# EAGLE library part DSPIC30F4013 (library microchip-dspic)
dsPIC General DSP with CAN and I2S ports
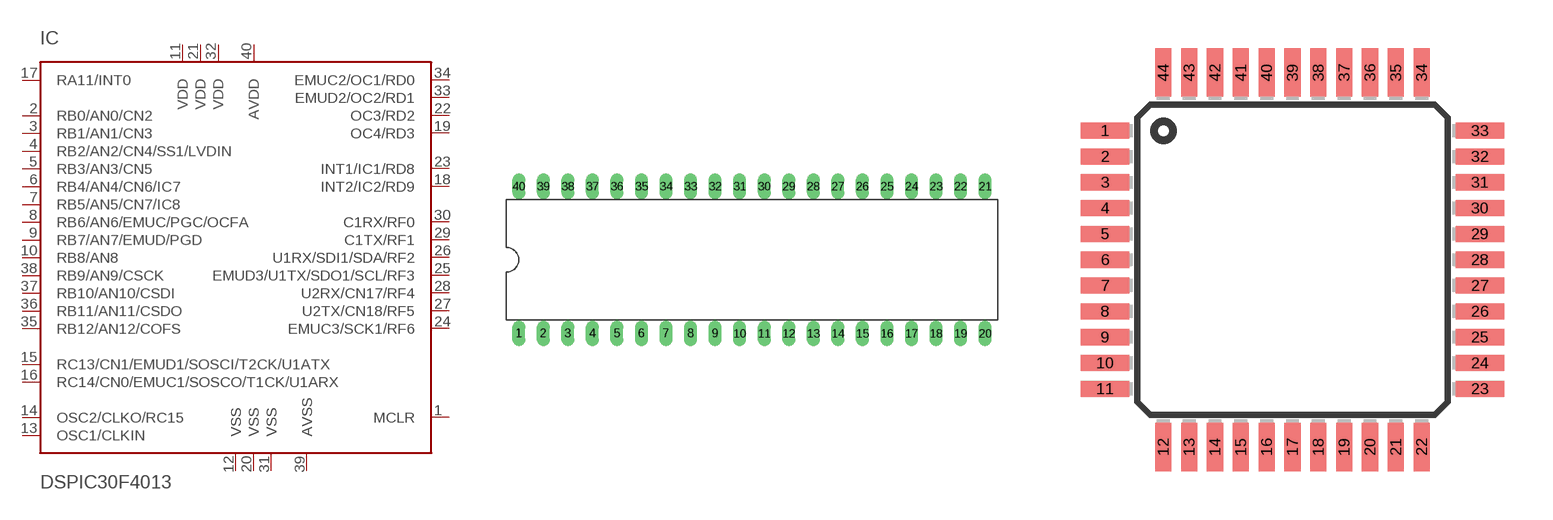
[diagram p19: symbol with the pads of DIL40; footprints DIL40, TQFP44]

Designator prefix IC

## DSPIC30F4013/P  [DIL40]
1  MCLR  in
2  RB0/AN0/CN2
3  RB1/AN1/CN3
4  RB2/AN2/CN4/SS1/LVDIN
5  RB3/AN3/CN5
6  RB4/AN4/CN6/IC7
7  RB5/AN5/CN7/IC8
8  RB6/AN6/EMUC/PGC/OCFA
9  RB7/AN7/EMUD/PGD
10  RB8/AN8
11  VDD  pwr
12  VSS  pwr
13  OSC1/CLKIN  in
14  OSC2/CLKO/RC15
15  RC13/CN1/EMUD1/SOSCI/T2CK/U1ATX
16  RC14/CN0/EMUC1/SOSCO/T1CK/U1ARX
17  RA11/INT0
18  INT2/IC2/RD9
19  OC4/RD3
20  VSS  pwr
21  VDD  pwr
22  OC3/RD2
23  INT1/IC1/RD8
24  EMUC3/SCK1/RF6
25  EMUD3/U1TX/SDO1/SCL/RF3
26  U1RX/SDI1/SDA/RF2
27  U2TX/CN18/RF5
28  U2RX/CN17/RF4
29  C1TX/RF1
30  C1RX/RF0
31  VSS  pwr
32  VDD  pwr
33  EMUD2/OC2/RD1
34  EMUC2/OC1/RD0
35  RB12/AN12/COFS
36  RB11/AN11/CSDO
37  RB10/AN10/CSDI
38  RB9/AN9/CSCK
39  AVSS  pwr
40  AVDD  pwr

## DSPIC30F4013/PT  [TQFP44]
1  U1RX/SDI1/SDA/RF2
2  U2TX/CN18/RF5
3  U2RX/CN17/RF4
4  C1TX/RF1
5  C1RX/RF0
6  VSS  pwr
7  VDD  pwr
8  EMUD2/OC2/RD1
9  EMUC2/OC1/RD0
10  RB12/AN12/COFS
11  RB11/AN11/CSDO
14  RB10/AN10/CSDI
15  RB9/AN9/CSCK
16  AVSS  pwr
17  AVDD  pwr
18  MCLR  in
19  RB0/AN0/CN2
20  RB1/AN1/CN3
21  RB2/AN2/CN4/SS1/LVDIN
22  RB3/AN3/CN5
23  RB4/AN4/CN6/IC7
24  RB5/AN5/CN7/IC8
25  RB6/AN6/EMUC/PGC/OCFA
26  RB7/AN7/EMUD/PGD
27  RB8/AN8
28  VDD  pwr
29  VSS  pwr
30  OSC1/CLKIN  in
31  OSC2/CLKO/RC15
32  RC13/CN1/EMUD1/SOSCI/T2CK/U1ATX
35  RC14/CN0/EMUC1/SOSCO/T1CK/U1ARX
36  RA11/INT0
37  INT2/IC2/RD9
38  OC4/RD3
39  VSS  pwr
40  VDD  pwr
41  OC3/RD2
42  INT1/IC1/RD8
43  EMUC3/SCK1/RF6
44  EMUD3/U1TX/SDO1/SCL/RF3

## DSPIC30F4013/ML  [QFN44-8X8]
1  U1RX/SDI1/SDA/RF2
2  U2TX/CN18/RF5
3  U2RX/CN17/RF4
4  C1TX/RF1
5  C1RX/RF0
6  VSS  pwr
7  VDD  pwr
9  EMUD2/OC2/RD1
10  EMUC2/OC1/RD0
11  RB12/AN12/COFS
12  RB11/AN11/CSDO
14  RB10/AN10/CSDI
15  RB9/AN9/CSCK
16  AVSS  pwr
17  AVDD  pwr
18  MCLR  in
19  RB0/AN0/CN2
20  RB1/AN1/CN3
21  RB2/AN2/CN4/SS1/LVDIN
22  RB3/AN3/CN5
23  RB4/AN4/CN6/IC7
24  RB5/AN5/CN7/IC8
25  RB6/AN6/EMUC/PGC/OCFA
26  RB7/AN7/EMUD/PGD
27  RB8/AN8
28  VDD  pwr
30  VSS  pwr
32  OSC1/CLKIN  in
33  OSC2/CLKO/RC15
34  RC13/CN1/EMUD1/SOSCI/T2CK/U1ATX
35  RC14/CN0/EMUC1/SOSCO/T1CK/U1ARX
36  RA11/INT0
37  INT2/IC2/RD9
38  OC4/RD3
39  VSS  pwr
40  VDD  pwr
41  OC3/RD2
42  INT1/IC1/RD8
43  EMUC3/SCK1/RF6
44  EMUD3/U1TX/SDO1/SCL/RF3

## Footprint DIL40 (pad centres in mm)
Dual In Line package type P
drill 0.813 long: 1 -24.13,-7.62; 2 -21.59,-7.62; 3 -19.05,-7.62; 4 -16.51,-7.62; 5 -13.97,-7.62; 6 -11.43,-7.62; 7 -8.89,-7.62; 8 -6.35,-7.62; 9 -3.81,-7.62; 10 -1.27,-7.62; 11 1.27,-7.62; 12 3.81,-7.62; 13 6.35,-7.62; 14 8.89,-7.62; 15 11.43,-7.62; 16 13.97,-7.62; 17 16.51,-7.62; 18 19.05,-7.62; 19 21.59,-7.62; 20 24.13,-7.62; 21 24.13,7.62; 22 21.59,7.62; 23 19.05,7.62; 24 16.51,7.62; 25 13.97,7.62; 26 11.43,7.62; 27 8.89,7.62; 28 6.35,7.62; 29 3.81,7.62; 30 1.27,7.62; 31 -1.27,7.62; 32 -3.81,7.62; 33 -6.35,7.62; 34 -8.89,7.62; 35 -11.43,7.62; 36 -13.97,7.62; 37 -16.51,7.62; 38 -19.05,7.62; 39 -21.59,7.62; 40 -24.13,7.62

## Footprint TQFP44 (pad centres in mm)
Thin Quad Flat Pack package type TQ
smd 1.5 x 0.5: 1 -5.8,4; 2 -5.8,3.2; 3 -5.8,2.4; 4 -5.8,1.6; 5 -5.8,0.8; 6 -5.8,0; 7 -5.8,-0.8; 8 -5.8,-1.6; 9 -5.8,-2.4; 10 -5.8,-3.2; 11 -5.8,-4; 23 5.8,-4; 24 5.8,-3.2; 25 5.8,-2.4; 26 5.8,-1.6; 27 5.8,-0.8; 28 5.8,0; 29 5.8,0.8; 30 5.8,1.6; 31 5.8,2.4; 32 5.8,3.2; 33 5.8,4
smd 0.5 x 1.5: 12 -4,-5.8; 13 -3.2,-5.8; 14 -2.4,-5.8; 15 -1.6,-5.8; 16 -0.8,-5.8; 17 0,-5.8; 18 0.8,-5.8; 19 1.6,-5.8; 20 2.4,-5.8; 21 3.2,-5.8; 22 4,-5.8; 34 4,5.8; 35 3.2,5.8; 36 2.4,5.8; 37 1.6,5.8; 38 0.8,5.8; 39 0,5.8; 40 -0.8,5.8; 41 -1.6,5.8; 42 -2.4,5.8; 43 -3.2,5.8; 44 -4,5.8

## Footprint QFN44-8X8 (pad centres in mm)
Quad Flat No Lead
smd 0.6 x 0.37: 1 3.825,-3.25; 2 3.825,-2.6; 3 3.825,-1.95; 4 3.825,-1.3; 5 3.825,-0.65; 6 3.825,0; 7 3.825,0.65; 8 3.825,1.3; 9 3.825,1.95; 10 3.825,2.6; 11 3.825,3.25; 23 -3.825,3.25; 24 -3.825,2.6; 25 -3.825,1.95; 26 -3.825,1.3; 27 -3.825,0.65; 28 -3.825,0; 29 -3.825,-0.65; 30 -3.825,-1.3; 31 -3.825,-1.95; 32 -3.825,-2.6; 33 -3.825,-3.25
smd 0.37 x 0.6: 12 3.25,3.825; 13 2.6,3.825; 14 1.95,3.825; 15 1.3,3.825; 16 0.65,3.825; 17 0,3.825; 18 -0.65,3.825; 19 -1.3,3.825; 20 -1.95,3.825; 21 -2.6,3.825; 22 -3.25,3.825; 34 -3.25,-3.825; 35 -2.6,-3.825; 36 -1.95,-3.825; 37 -1.3,-3.825; 38 -0.65,-3.825; 39 0,-3.825; 40 0.65,-3.825; 41 1.3,-3.825; 42 1.95,-3.825; 43 2.6,-3.825; 44 3.25,-3.825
